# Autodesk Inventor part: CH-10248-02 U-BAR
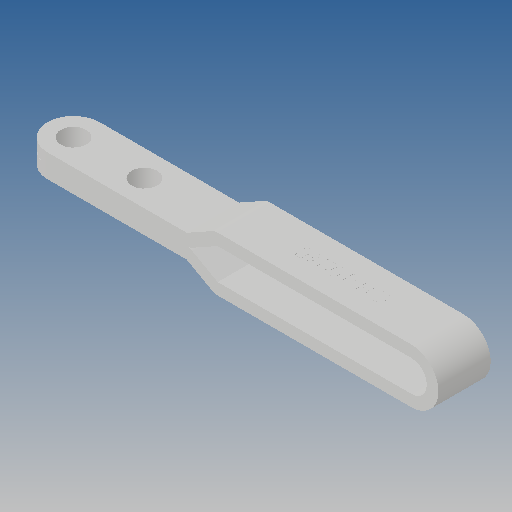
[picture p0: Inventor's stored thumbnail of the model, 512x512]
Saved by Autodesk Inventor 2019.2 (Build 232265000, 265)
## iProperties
Created: 2012-09
Part Number: CH-10248-02 U-BAR
Material: Ogólny
Document SubType Name: Modeling
Designer: CADENGINEERING4
Density: 1 g/cm^3
Appearance: Domyślna
Author: CADENGINEERING4
Revision Number: ÈÎºÎ
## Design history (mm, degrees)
feature "ÇÐ³ý-À­Éì4"
feature "ÇÐ³ý-À­Éì5"
node "Bryła1"
node "Bryła2"
